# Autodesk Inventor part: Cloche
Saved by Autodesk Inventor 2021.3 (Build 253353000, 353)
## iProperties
Created: 2022-06
Part Number: Cloche
Material: Generic
Document SubType Name: Modeling
Designer: Administrator
Density: 1 g/cm^3
Appearance: Default
Title: Cloche v2
Author: Administrator
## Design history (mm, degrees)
feature "Cloche" [Body]
feature "Socket Body" [Body]
feature "Shade Ring" [Body]
feature "Shade Ring +Collar" [Body]
feature "Socket" [Body]
feature "Body1"
feature "Metal Strain Relief" [Body]
feature "Fabric Cord (1)" [Body]
feature "Stem (Threaded)" [Body]
feature "Cap (Threaded)" [Body]
feature "5M Set Screw" [Body]
feature "T9-Bulb" [Body]
body "Solid1"
body "Solid2"
body "Solid3"
body "Solid4"
body "Solid5"
body "Solid6"
body "Solid7"
body "Solid8"
body "Solid9"
body "Solid10"
body "Solid11"
body "Solid12"
